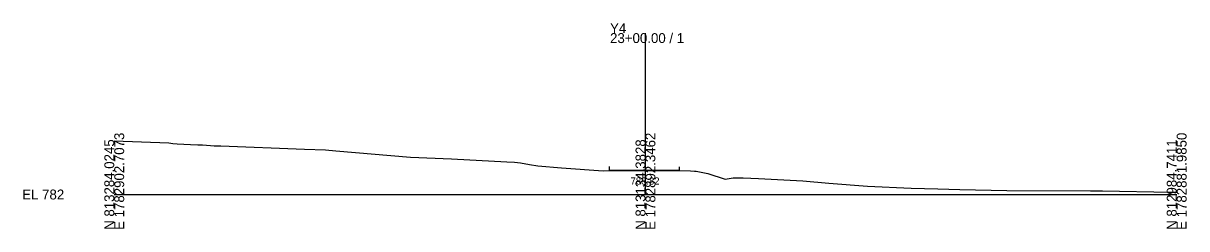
# Model space of a CAD drawing. Extents: x -26 to 3903, y -10 to 9562.
# Drawn here: x 974.3 to 1302.8, y 5490.3 to 5548.4 of the extents above; entities that cross this region are included whole.
import ezdxf

# ---------------------------------------------------------------- set-up
doc = ezdxf.new("R2010")
doc.units = 0
for name, color, linetype in [('Exist Cross Section Cell', 7, 'Continuous'), ('Exist XS Center Line Elevation Label', 7, 'Continuous'), ('Exist XS Ground Line', 7, 'Continuous'), ('Prop XS EOT Tick Mark', 7, 'Continuous'), ('Prop XS Finish Grade Pavement', 7, 'Continuous')]:
    doc.layers.add(name, color=color, linetype=linetype)

msp = doc.modelspace()

# ---------------------------------------------------------------- linework, layer by layer
at = {"layer": 'Exist Cross Section Cell'}
for p, q in [((1150, 5500), (1150, 5545.64)), ((1000, 5500), (1150, 5500)), ((1150, 5500), (1300, 5500))]:
    msp.add_line(p, q, dxfattribs=at)
at = {"layer": 'Exist XS Ground Line'}
for p, q in [((1000, 5515.21), (1015.37, 5514.63)), ((1015.37, 5514.63), (1016.53, 5514.44)), ((1016.53, 5514.44), (1017.79, 5514.34)), ((1017.79, 5514.34), (1019.69, 5514.21)), ((1019.69, 5514.21), (1021.55, 5514.14)), ((1021.55, 5514.14), (1023.57, 5514.08)), ((1023.57, 5514.08), (1024.89, 5514)), ((1024.89, 5514), (1027.2, 5513.86)), ((1027.2, 5513.86), (1028.24, 5513.8)), ((1028.24, 5513.8), (1030.07, 5513.73)), ((1030.07, 5513.73), (1053.73, 5512.84)), ((1053.73, 5512.84), (1059.68, 5512.62)), ((1059.68, 5512.62), (1062.56, 5512.39)), ((1062.56, 5512.39), (1083.63, 5510.55)), ((1083.63, 5510.55), (1095.25, 5510.11)), ((1095.25, 5510.11), (1110.84, 5509.28)), ((1110.84, 5509.28), (1113, 5509.12)), ((1113, 5509.12), (1114.68, 5508.94)), ((1114.68, 5508.94), (1117.27, 5508.47)), ((1117.27, 5508.47), (1119.57, 5508.12)), ((1119.57, 5508.12), (1126.28, 5507.56)), ((1126.28, 5507.56), (1138.06, 5506.68)), ((1138.06, 5506.68), (1139.79, 5506.77)), ((1139.79, 5506.77), (1141.05, 5506.78)), ((1141.05, 5506.78), (1149.44, 5506.82)), ((1149.44, 5506.82), (1150, 5506.82)), ((1150, 5506.82), (1154.13, 5506.8)), ((1154.13, 5506.8), (1159.58, 5506.75)), ((1159.58, 5506.75), (1162.73, 5506.66)), ((1162.73, 5506.66), (1163.82, 5506.63)), ((1163.82, 5506.63), (1164.27, 5506.62)), ((1164.27, 5506.62), (1167.6, 5505.98)), ((1167.6, 5505.98), (1172.5, 5504.29)), ((1172.5, 5504.29), (1174.72, 5504.71)), ((1174.72, 5504.71), (1177.6, 5504.74)), ((1177.6, 5504.74), (1181.9, 5504.52)), ((1181.9, 5504.52), (1194.46, 5503.86)), ((1194.46, 5503.86), (1201.78, 5503.19)), ((1201.78, 5503.19), (1212.67, 5502.4)), ((1212.67, 5502.4), (1225.07, 5501.82)), ((1225.07, 5501.82), (1232.59, 5501.62)), ((1232.59, 5501.62), (1238.75, 5501.45)), ((1238.75, 5501.45), (1252.01, 5501.11)), ((1252.01, 5501.11), (1275.62, 5501.03)), ((1275.62, 5501.03), (1278.63, 5501.04)), ((1278.63, 5501.04), (1279.06, 5500.99)), ((1279.06, 5500.99), (1298.37, 5500.65)), ((1298.37, 5500.65), (1300, 5500.62))]:
    msp.add_line(p, q, dxfattribs=at)
at = {"layer": 'Prop XS EOT Tick Mark'}
for p, q in [((1139.82, 5506.9), (1139.82, 5507.9)), ((1159.61, 5506.87), (1159.61, 5507.87))]:
    msp.add_line(p, q, dxfattribs=at)
at = {"layer": 'Prop XS Finish Grade Pavement'}
for p, q in [((1139.82, 5506.9), (1141.05, 5506.91)), ((1141.05, 5506.91), (1149.44, 5506.95)), ((1149.44, 5506.95), (1150, 5506.94)), ((1150, 5506.94), (1154.13, 5506.92)), ((1154.13, 5506.92), (1159.58, 5506.88)), ((1159.58, 5506.88), (1159.61, 5506.87))]:
    msp.add_line(p, q, dxfattribs=at)

# ---------------------------------------------------------------- texts
at = {"layer": 'Exist Cross Section Cell'}
for s, p in [('Y4', (1140, 5545.64)), ('23+00.00 / 1', (1140, 5542.84)), ('EL 782', (974, 5498.6))]:
    msp.add_text(s, height=2.8, dxfattribs=at).set_placement(p)
for s, p in [('E 1782902.7073', (1002.8, 5490)), ('E 1782892.3462', (1152.8, 5490)), ('E 1782881.9850', (1302.8, 5490)), ('N 813284.0245', (1000, 5490)), ('N 813134.3828', (1150, 5490)), ('N 812984.7411', (1300, 5490))]:
    msp.add_text(s, height=2.8, rotation=90, dxfattribs=at).set_placement(p)
at = {"layer": 'Exist XS Center Line Elevation Label'}
msp.add_text('788.82', height=2, dxfattribs=at).set_placement((1145.79, 5502.82))

doc.saveas('drawing.dxf')
